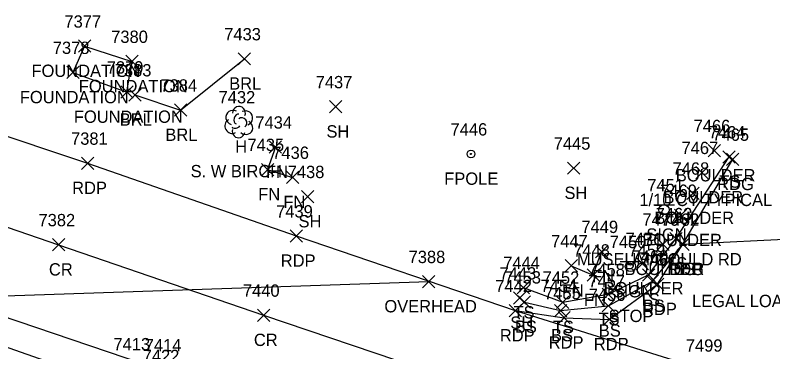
# Model space of a CAD drawing. Extents: x 1611797 to 1633212, y 298978 to 305475.
# Drawn here: x 1625007.5 to 1625130.4, y 304419 to 304473.6 of the extents above; entities that cross this region are included whole.
import ezdxf

# ---------------------------------------------------------------- set-up
doc = ezdxf.new("R2010")
doc.units = 0
for name, color, linetype in [('DCP', 7, 'Continuous'), ('L_A', 7, 'Continuous'), ('L_C', 7, 'Continuous'), ('L_I', 7, 'Continuous'), ('L_TIC', 7, 'Continuous'), ('LABL', 7, 'Continuous'), ('LBC', 7, 'Continuous'), ('LELB', 7, 'Continuous'), ('LFNC', 7, 'Continuous'), ('LFP', 7, 'Continuous'), ('LTD', 7, 'Continuous'), ('P_A', 7, 'Continuous'), ('P_I', 7, 'Continuous'), ('P_TIC', 7, 'Continuous'), ('PET', 7, 'Continuous'), ('PEU', 7, 'Continuous'), ('PRC', 7, 'Continuous'), ('R_I', 7, 'Continuous'), ('S_A', 7, 'Continuous'), ('S_C', 7, 'Continuous'), ('S_I', 7, 'Continuous'), ('SSGN', 7, 'Continuous'), ('U_A', 7, 'Continuous'), ('U_I', 7, 'Continuous'), ('U_TIC', 7, 'Continuous'), ('UCO', 7, 'Continuous')]:
    doc.layers.add(name, color=color, linetype=linetype)

msp = doc.modelspace()

# ---------------------------------------------------------------- linework, layer by layer
at = {"layer": 'DCP'}
msp.add_lwpolyline([(1624994.71, 304423.73), (1625026.87, 304412.45)], dxfattribs=at)
at = {"layer": 'L_TIC'}
for points in [[(1625017.72, 304467.61), (1625019.72, 304469.61)], [(1625019.72, 304467.61), (1625017.72, 304469.61)], [(1625017.72, 304467.61), (1625019.72, 304469.61)], [(1625019.72, 304467.61), (1625017.72, 304469.61)], [(1625025.4, 304465.13), (1625027.4, 304467.13)], [(1625027.4, 304465.13), (1625025.4, 304467.13)], [(1625025.4, 304465.13), (1625027.4, 304467.13)], [(1625027.4, 304465.13), (1625025.4, 304467.13)], [(1625043.66, 304465.55), (1625045.66, 304467.55)], [(1625045.66, 304465.55), (1625043.66, 304467.55)], [(1625015.83, 304463.34), (1625017.83, 304465.34)], [(1625017.83, 304463.34), (1625015.83, 304465.34)], [(1625024.6, 304460.16), (1625026.6, 304462.16)], [(1625026.6, 304460.16), (1625024.6, 304462.16)], [(1625025.89, 304459.7), (1625027.89, 304461.7)], [(1625027.89, 304459.7), (1625025.89, 304461.7)], [(1625058.5, 304457.77), (1625060.5, 304459.77)], [(1625060.5, 304457.77), (1625058.5, 304459.77)], [(1625033.3, 304457.23), (1625035.3, 304459.23)], [(1625035.3, 304457.23), (1625033.3, 304459.23)], [(1625048.7, 304451.22), (1625050.7, 304453.22)], [(1625050.7, 304451.22), (1625048.7, 304453.22)], [(1625119.94, 304450.65), (1625121.94, 304452.65)], [(1625121.94, 304450.65), (1625119.94, 304452.65)], [(1625122.34, 304449.63), (1625124.34, 304451.63)], [(1625124.34, 304449.63), (1625122.34, 304451.63)], [(1625097.13, 304447.8), (1625099.13, 304449.8)], [(1625099.13, 304447.8), (1625097.13, 304449.8)], [(1625047.43, 304447.58), (1625049.43, 304449.58)], [(1625049.43, 304447.58), (1625047.43, 304449.58)], [(1625117.93, 304447.09), (1625119.93, 304449.09)], [(1625119.93, 304447.09), (1625117.93, 304449.09)], [(1625051.5, 304446.31), (1625053.5, 304448.31)], [(1625053.5, 304446.31), (1625051.5, 304448.31)], [(1625053.96, 304443.19), (1625055.96, 304445.19)], [(1625055.96, 304443.19), (1625053.96, 304445.19)], [(1625116.47, 304443.74), (1625118.47, 304445.74)], [(1625118.47, 304443.74), (1625116.47, 304445.74)], [(1625114.48, 304440.14), (1625116.48, 304442.14)], [(1625116.48, 304440.14), (1625114.48, 304442.14)], [(1625111.62, 304435.45), (1625113.62, 304437.45)], [(1625113.62, 304435.45), (1625111.62, 304437.45)], [(1625113.72, 304436.35), (1625115.72, 304438.35)], [(1625115.72, 304436.35), (1625113.72, 304438.35)], [(1625114.84, 304435.44), (1625116.84, 304437.44)], [(1625116.84, 304435.44), (1625114.84, 304437.44)], [(1625101.64, 304434.27), (1625103.64, 304436.27)], [(1625103.64, 304434.27), (1625101.64, 304436.27)], [(1625096.71, 304431.95), (1625098.71, 304433.95)], [(1625098.71, 304431.95), (1625096.71, 304433.95)], [(1625108.25, 304432.32), (1625110.25, 304434.32)], [(1625110.25, 304432.32), (1625108.25, 304434.32)], [(1625100.3, 304430.45), (1625102.3, 304432.45)], [(1625102.3, 304430.45), (1625100.3, 304432.45)], [(1625109.28, 304430.47), (1625111.28, 304432.47)], [(1625111.28, 304430.47), (1625109.28, 304432.47)], [(1625109.9, 304429.46), (1625111.9, 304431.46)], [(1625111.9, 304429.46), (1625109.9, 304431.46)], [(1625088.94, 304428.41), (1625090.94, 304430.41)], [(1625090.94, 304428.41), (1625088.94, 304430.41)], [(1625088.34, 304426.72), (1625090.34, 304428.72)], [(1625090.34, 304426.72), (1625088.34, 304428.72)], [(1625102.73, 304427.32), (1625104.73, 304429.32)], [(1625104.73, 304427.32), (1625102.73, 304429.32)], [(1625089.12, 304426.07), (1625091.12, 304428.07)], [(1625091.12, 304426.07), (1625089.12, 304428.07)], [(1625095.33, 304426.03), (1625097.33, 304428.03)], [(1625097.33, 304426.03), (1625095.33, 304428.03)], [(1625095, 304424.69), (1625097, 304426.69)], [(1625097, 304424.69), (1625095, 304426.69)], [(1625102.75, 304425.45), (1625104.75, 304427.45)], [(1625104.75, 304425.45), (1625102.75, 304427.45)]]:
    msp.add_lwpolyline(points, dxfattribs=at)
at = {"layer": 'LABL'}
msp.add_lwpolyline([(1625026.89, 304460.7), (1625034.3, 304458.23), (1625044.66, 304466.55)], dxfattribs=at)
at = {"layer": 'LBC'}
for points in [[(1625018.72, 304468.61), (1625016.83, 304464.34), (1625025.6, 304461.16), (1625026.4, 304466.13)], [(1625018.72, 304468.61), (1625026.4, 304466.13)]]:
    msp.add_lwpolyline(points, dxfattribs=at)
at = {"layer": 'LELB'}
for points in [[(1625089.94, 304429.41), (1625096.33, 304427.03), (1625103.73, 304428.32), (1625110.28, 304431.47), (1625114.72, 304437.35), (1625123.34, 304450.63)], [(1625090.12, 304427.07), (1625096, 304425.69), (1625103.75, 304426.45), (1625110.9, 304430.46), (1625115.84, 304436.44)]]:
    msp.add_lwpolyline(points, dxfattribs=at)
at = {"layer": 'LFNC'}
for points in [[(1625049.7, 304452.22), (1625048.43, 304448.58), (1625052.5, 304447.31)], [(1625097.71, 304432.95), (1625101.3, 304431.45), (1625102.64, 304435.27)]]:
    msp.add_lwpolyline(points, dxfattribs=at)
at = {"layer": 'LFP'}
for radius in [0.625, 0.0833]:
    msp.add_circle((1625081.44, 304451.1), radius, dxfattribs=at)
at = {"layer": 'LTD'}
msp.add_line((1625043.74, 304456.32), (1625043.74, 304456.32), dxfattribs=at)
msp.add_line((1625043.74, 304456.32), (1625043.74, 304456.32), dxfattribs=at)
msp.add_arc((1625043.78, 304457.76), 1.05, 335.5272, 180.9563, dxfattribs=at)
for centre, major_axis, ratio, start_param, end_param in [((1625042.95, 304456.99), (1.21, -0.51), 0.895232, 1.570796, 4.712389), ((1625044.78, 304456.91), (-1.14, -0.48), 0.949671, 1.570796, 4.712389), ((1625043.53, 304456.78), (-0.208, -0.792), 0.645439, 3.141593, 6.283185), ((1625044.24, 304456.16), (-0.5, 0.667), 0.989748, 3.141593, 6.283185), ((1625042.65, 304455.61), (0.58, -1.04), 0.959034, 3.141593, 6.283185), ((1625044.74, 304455.49), (-1.09, 0.79), 0.841452, 1.570796, 4.712389), ((1625043.74, 304454.82), (0.26, 1.06), 0.942809, 1.570796, 4.712389), ((1625043.28, 304455.57), (-0.625, -0.083), 0.423636, 0, 3.141593)]:
    msp.add_ellipse(centre, major_axis=major_axis, ratio=ratio, start_param=start_param, end_param=end_param, dxfattribs=at)
at = {"layer": 'P_TIC'}
for points in [[(1625122.92, 304449.24), (1625124.92, 304451.24)], [(1625124.92, 304449.24), (1625122.92, 304451.24)], [(1625018.22, 304448.6), (1625020.22, 304450.6)], [(1625020.22, 304448.6), (1625018.22, 304450.6)], [(1625052.09, 304436.79), (1625054.09, 304438.79)], [(1625054.09, 304436.79), (1625052.09, 304438.79)], [(1625013.51, 304435.37), (1625015.51, 304437.37)], [(1625015.51, 304435.37), (1625013.51, 304437.37)], [(1625114.84, 304435.44), (1625116.84, 304437.44)], [(1625116.84, 304435.44), (1625114.84, 304437.44)], [(1625114.84, 304435.44), (1625116.84, 304437.44)], [(1625116.84, 304435.44), (1625114.84, 304437.44)], [(1625110.72, 304428.95), (1625112.72, 304430.95)], [(1625112.72, 304428.95), (1625110.72, 304430.95)], [(1625087.64, 304424.67), (1625089.64, 304426.67)], [(1625089.64, 304424.67), (1625087.64, 304426.67)], [(1625087.64, 304424.67), (1625089.64, 304426.67)], [(1625089.64, 304424.67), (1625087.64, 304426.67)], [(1625046.78, 304423.93), (1625048.78, 304425.93)], [(1625048.78, 304423.93), (1625046.78, 304425.93)], [(1625095.57, 304423.51), (1625097.57, 304425.51)], [(1625097.57, 304423.51), (1625095.57, 304425.51)], [(1625102.89, 304423.25), (1625104.89, 304425.25)], [(1625104.89, 304423.25), (1625102.89, 304425.25)]]:
    msp.add_lwpolyline(points, dxfattribs=at)
at = {"layer": 'PET'}
for points in [[(1624984.5, 304461.2), (1625019.22, 304449.6), (1625053.09, 304437.79), (1625088.64, 304425.67), (1625119.58, 304416.01), (1625145.16, 304407.53), (1625162.83, 304401.91), (1625203.9, 304387.79), (1625240.11, 304375.18), (1625270.8, 304364.7), (1625305.42, 304352.67), (1625347.33, 304338.27), (1625377.45, 304327.63), (1625419.06, 304313.11), (1625456.66, 304299.5), (1625486.48, 304288.52), (1625520.4, 304276.8), (1625561.48, 304263.44), (1625586.31, 304255.91), (1625607.81, 304248.69)], [(1625088.64, 304425.67), (1625096.57, 304424.51), (1625103.89, 304424.25), (1625111.72, 304429.95), (1625115.84, 304436.44), (1625135.57, 304437.44), (1625133.9, 304430.73), (1625133.76, 304424.17), (1625136.49, 304416.99), (1625145.16, 304407.53)], [(1624996.18, 304427.92), (1625031.18, 304416.05), (1625054.11, 304408.39), (1625092.54, 304395.66), (1625128.39, 304383.43), (1625154.43, 304374.87), (1625186.48, 304364.34), (1625228.16, 304349.71), (1625241.38, 304345.3), (1625257.71, 304339.55), (1625294.06, 304327), (1625336.12, 304312.5), (1625367.07, 304301.52), (1625409.49, 304287.06), (1625446.99, 304273.72), (1625476.12, 304263.37), (1625510.55, 304251.43), (1625557.47, 304235.65), (1625560.62, 304234.67), (1625582, 304228.03), (1625604.38, 304221.93)]]:
    msp.add_lwpolyline(points, dxfattribs=at)
at = {"layer": 'PEU'}
msp.add_lwpolyline([(1625115.84, 304436.44), (1625123.92, 304450.24)], dxfattribs=at)
at = {"layer": 'PRC'}
msp.add_lwpolyline([(1624974.99, 304449.94), (1625014.51, 304436.37), (1625047.78, 304424.93), (1625083.75, 304412.75), (1625119.62, 304401.19), (1625142.09, 304393.34), (1625157.77, 304388.18), (1625199.46, 304373.62), (1625235.03, 304361.94), (1625264.49, 304351.45), (1625300.09, 304339.34), (1625341.97, 304324.72), (1625371.92, 304313.89), (1625413.56, 304299.21), (1625451.48, 304285.65), (1625480.77, 304275.38), (1625515.11, 304263.78), (1625560.63, 304248.88), (1625591.76, 304239.18), (1625621.07, 304231.02)], dxfattribs=at)
at = {"layer": 'SSGN'}
for p, q in [((1625111.13, 304442.87), (1625114.46, 304442.87)), ((1625112.77, 304442.04), (1625112.77, 304442.04)), ((1625105.68, 304433.67), (1625109.01, 304433.67)), ((1625107.32, 304432.84), (1625107.32, 304432.84))]:
    msp.add_line(p, q, dxfattribs=at)
for centre in [(1625112.77, 304442.04), (1625107.32, 304432.84)]:
    msp.add_circle(centre, 0.833, dxfattribs=at)
at = {"layer": 'U_TIC'}
for points in [[(1625073.58, 304429.39), (1625075.58, 304431.39)], [(1625075.58, 304429.39), (1625073.58, 304431.39)]]:
    msp.add_lwpolyline(points, dxfattribs=at)
at = {"layer": 'UCO'}
msp.add_lwpolyline([(1624996.13, 304427.75), (1625074.58, 304430.39)], dxfattribs=at)

# ---------------------------------------------------------------- texts
at = {"layer": 'L_A'}
for s, p in [('FOUNDATION', (1625010.11, 304463.61)), ('FOUNDATION', (1625010.11, 304463.61)), ('FOUNDATION', (1625017.79, 304461.13)), ('FOUNDATION', (1625017.79, 304461.13)), ('BRL', (1625042.2, 304461.55)), ('FOUNDATION', (1625008.22, 304459.34)), ('FOUNDATION', (1625016.99, 304456.16)), ('BRL', (1625024.43, 304455.7)), ('SH', (1625057.99, 304453.77)), ('BRL', (1625031.84, 304453.23)), ('H', (1625043.17, 304451.32)), ('FN', (1625048.18, 304447.22)), ('BOULDER', (1625114.69, 304446.65)), ('FPOLE', (1625077.11, 304446.1)), ('TS', (1625121.75, 304445.63)), ('FN', (1625046.91, 304443.58)), ('SH', (1625096.62, 304443.8)), ('BOULDER', (1625112.69, 304443.09)), ('FN', (1625050.98, 304442.31)), ('SH', (1625053.45, 304439.19)), ('BOULDER', (1625111.22, 304439.74)), ('BOULDER', (1625109.24, 304436.14)), ('TS', (1625113.13, 304432.35)), ('BOULDER', (1625106.37, 304431.45)), ('BS', (1625114.28, 304431.44)), ('FN', (1625101.12, 304430.27)), ('FN', (1625096.19, 304427.95)), ('BOULDER', (1625103, 304428.32)), ('FN', (1625099.78, 304426.45)), ('TS', (1625108.69, 304426.47)), ('BS', (1625109.34, 304425.46)), ('TS', (1625088.35, 304424.41)), ('TS', (1625102.14, 304423.32)), ('SH', (1625087.83, 304422.72)), ('BS', (1625088.56, 304422.07)), ('TS', (1625094.74, 304422.03)), ('BS', (1625094.44, 304420.69)), ('BS', (1625102.19, 304421.45))]:
    msp.add_text(s, height=2, dxfattribs=at).set_placement(p)
at = {"layer": 'L_C'}
for s, p in [('S. W BIRCH', (1625035.94, 304447.32)), ('1/10 CY TYPICAL', (1625108.78, 304442.65))]:
    msp.add_text(s, height=2, dxfattribs=at).set_placement(p)
at = {"layer": 'L_I'}
for s, p in [('7377', (1625015.46, 304471.61)), ('7377', (1625015.46, 304471.61)), ('7380', (1625023.05, 304469.13)), ('7380', (1625023.05, 304469.13)), ('7433', (1625041.4, 304469.55)), ('7378', (1625013.57, 304467.34)), ('7379', (1625022.33, 304464.16)), ('7383', (1625023.63, 304463.7)), ('7384', (1625031.04, 304461.23)), ('7437', (1625056.24, 304461.77)), ('7432', (1625040.48, 304459.32)), ('7434', (1625046.44, 304455.22)), ('7446', (1625078.13, 304454.1)), ('7466', (1625117.58, 304454.65)), ('7464', (1625120.03, 304453.63)), ('7435', (1625045.17, 304451.58)), ('7445', (1625094.87, 304451.8)), ('7436', (1625049.19, 304450.31)), ('7467', (1625115.62, 304451.09)), ('7468', (1625114.16, 304447.74)), ('7438', (1625051.7, 304447.19)), ('7469', (1625112.16, 304444.14)), ('7463', (1625111.42, 304440.35)), ('7470', (1625109.27, 304439.45)), ('7462', (1625112.53, 304439.44)), ('7449', (1625099.37, 304438.27)), ('7447', (1625094.45, 304435.95)), ('7471', (1625106.55, 304436.32)), ('7448', (1625098.04, 304434.45)), ('7459', (1625107.01, 304434.47)), ('7460', (1625107.51, 304433.46)), ('7444', (1625086.68, 304432.41)), ('7443', (1625086.08, 304430.72)), ('7458', (1625100.47, 304431.32)), ('7453', (1625086.86, 304430.07)), ('7452', (1625093.07, 304430.03)), ('7457', (1625100.49, 304429.45)), ('7454', (1625092.74, 304428.69)), ('7422', (1625028.16, 304417.31))]:
    msp.add_text(s, height=2, dxfattribs=at).set_placement(p)
at = {"layer": 'P_A'}
for s, p in [('RDG', (1625121.41, 304445.24)), ('RDP', (1625016.71, 304444.6)), ('RDP', (1625050.57, 304432.79)), ('CR', (1625012.94, 304431.37)), ('RDG', (1625113.33, 304431.44)), ('RDP', (1625113.33, 304431.44)), ('RDP', (1625109.21, 304424.95)), ('RDP', (1625086.13, 304420.67)), ('RDP', (1625086.13, 304420.67)), ('CR', (1625046.21, 304419.93)), ('RDP', (1625094.06, 304419.51)), ('RDP', (1625101.38, 304419.25))]:
    msp.add_text(s, height=2, dxfattribs=at).set_placement(p)
at = {"layer": 'P_I'}
for s, p in [('7381', (1625016.53, 304452.6)), ('7465', (1625120.62, 304453.24)), ('7439', (1625049.82, 304440.79)), ('7382', (1625011.25, 304439.37)), ('7462', (1625112.53, 304439.44)), ('7462', (1625112.53, 304439.44)), ('7461', (1625108.98, 304432.95)), ('7440', (1625044.43, 304427.93)), ('7442', (1625085.38, 304428.67)), ('7442', (1625085.38, 304428.67)), ('7455', (1625093.31, 304427.51)), ('7456', (1625100.57, 304427.25)), ('7414', (1625028.49, 304419.05)), ('7499', (1625116.32, 304419.01))]:
    msp.add_text(s, height=2, dxfattribs=at).set_placement(p)
at = {"layer": 'R_I'}
for s, p in [('7413', (1625023.42, 304419.23)), ('7414', (1625028.49, 304419.05))]:
    msp.add_text(s, height=2, dxfattribs=at).set_placement(p)
at = {"layer": 'S_A'}
for p in [(1625109.91, 304437.02), (1625104.46, 304427.82)]:
    msp.add_text('SIGN', height=2, dxfattribs=at).set_placement(p)
at = {"layer": 'S_C'}
for s, p in [('MUSEUM/GOULD RD', (1625098.64, 304433.02)), ('LEGAL LOAD LIMIT 16000 POUNDS', (1625117.33, 304426.24)), ('STOP', (1625103.78, 304423.82))]:
    msp.add_text(s, height=2, dxfattribs=at).set_placement(p)
at = {"layer": 'S_I'}
for s, p in [('7451', (1625110.06, 304445.02)), ('7450', (1625103.96, 304435.82))]:
    msp.add_text(s, height=2, dxfattribs=at).set_placement(p)
at = {"layer": 'U_A'}
msp.add_text('OVERHEAD', height=2, dxfattribs=at).set_placement((1625067.39, 304425.39))
at = {"layer": 'U_I'}
msp.add_text('7388', height=2, dxfattribs=at).set_placement((1625071.32, 304433.39))

doc.saveas('drawing.dxf')
